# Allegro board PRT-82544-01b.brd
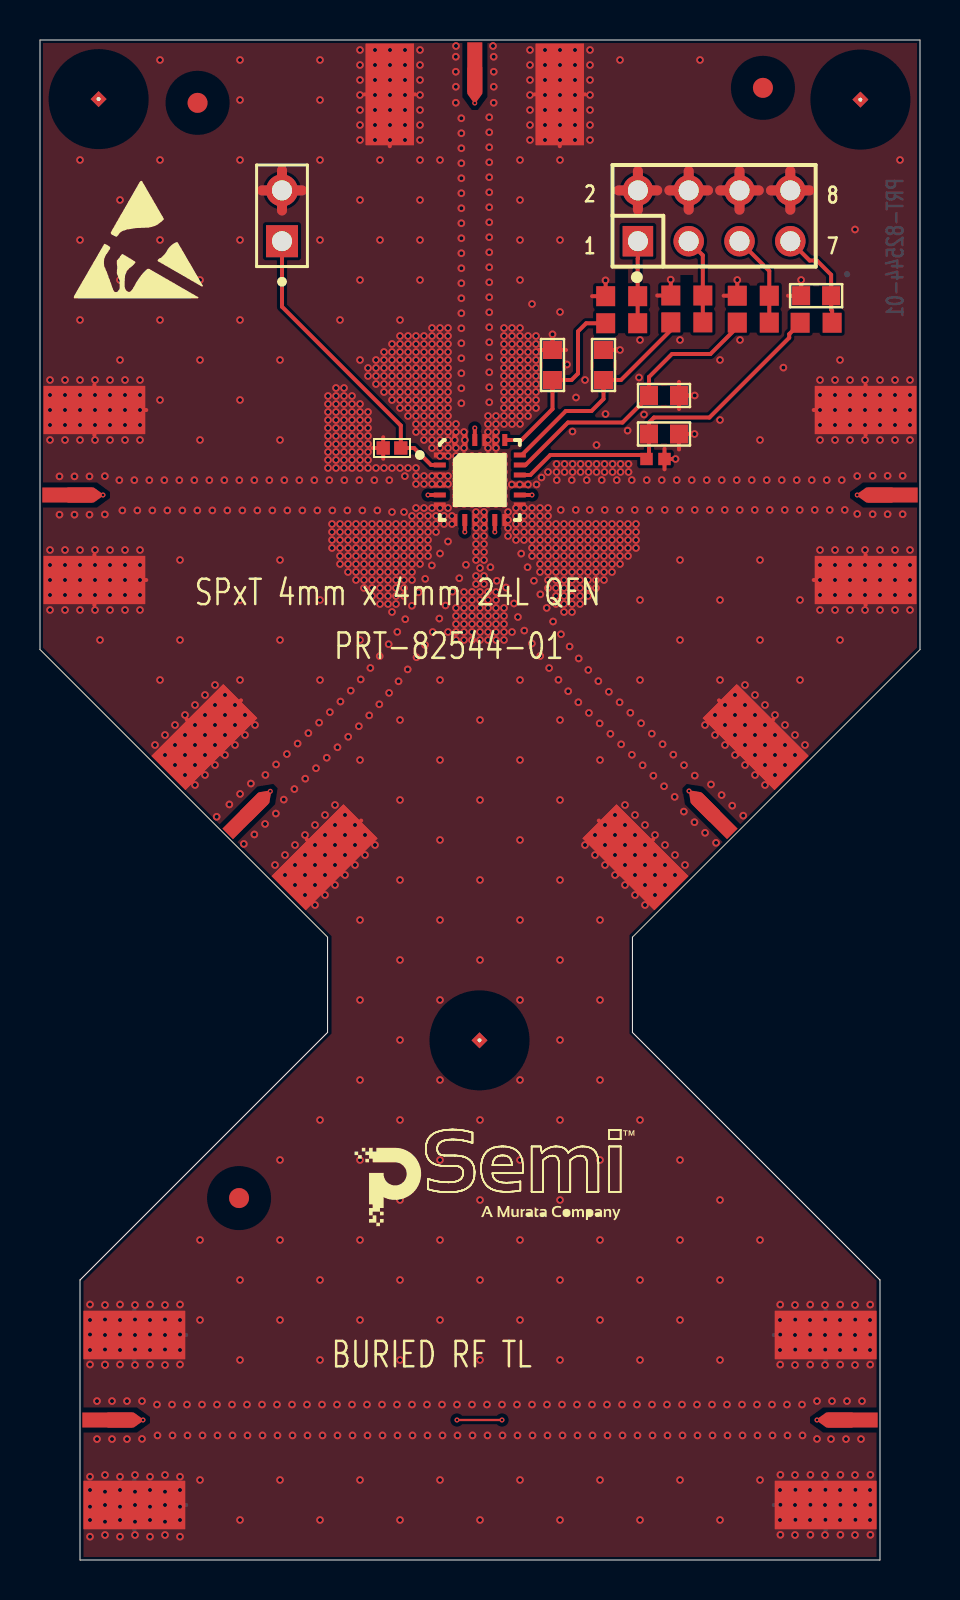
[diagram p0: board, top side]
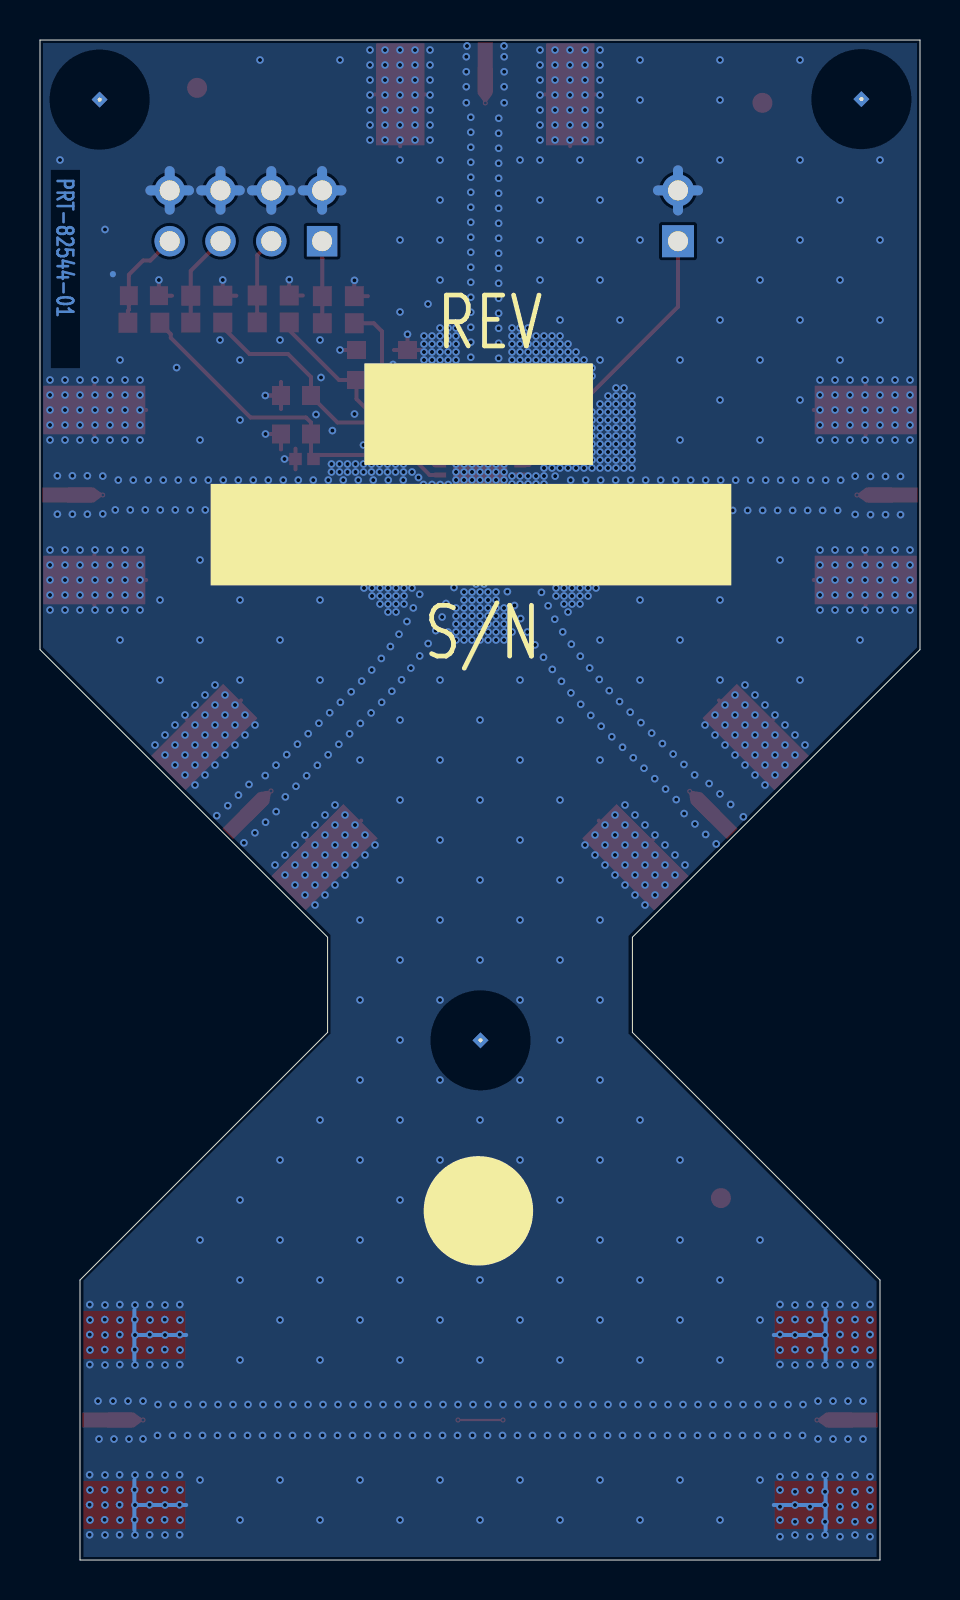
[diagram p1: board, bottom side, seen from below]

Outline 44 x 76 mm; copper layers: TOP, INNER LAYER 2, INNER LAYER 3, BOTTOM. Coordinates in mm from the lower left corner of the outline.
Outline path: 0,76 0,45.52 14.38,31.14 14.38,26.38 2,14 2,0 42,0 42,14 29.62,26.38 29.62,31.14 44,45.52 44,76 0,76

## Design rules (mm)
constraint set DEFAULT: 
nets with their own width: nets TE V1 V2 V3

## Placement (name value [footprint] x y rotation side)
C1  -  [CAPC1608X90N]  25.62 59.75 90 top
C2  -  [CAPC1608X90N]  28.18 59.75 90 top
C3  -  [CAPC1608X90N]  31.2 58.23 0 top
C4  -  [CAPC1608X90N]  31.2 56.3 0 top
C5  -  [CAPC1608X90N]  38.81 63.21 180 top
C7  -  [CAPC1005X55N]  30.77 55.05 0 top
J1  -  [SULLINS_PBC01DABN]  12.1 65.94 0 top
J2  -  [HDR2X4]  29.9 65.94 0 top
NOREF  -  []  0 76 0 top
NOREF#2  -  [unnamed#2]  21.98 25.98 0 top
NOREF#3  -  [unnamed#2]  2.93 73.05 0 top
NOREF#4  -  []  4.9 65.8 0 top
NOREF#5  -  [unnamed#2]  36.15 73.61 0 top
NOREF#6  -  []  -179.88 -98.6 0 top
NOREF#7  -  []  42 0 90 top
NOREF#8  -  []  57.15 54.8 0 top
NOREF#9  -  []  -191.92 -127.32 0 top
NOREF#10  -  [unnamed#2]  41.02 73.02 0 top
NOREF#11  -  [unnamed#2]  9.95 18.1 0 top
NOREF#12  -  []  -46.58 -55.22 0 top
NOREF#13  -  []  15.72 16.61 0 top
NOREF#14  -  [unnamed#2]  7.88 72.86 0 top
NOREF#15  -  []  22.12 17.4 180 bottom
NOREF#16  -  []  3.36 41.06 180 bottom
R1  -  [RESC1608X55N]  29.08 61.84 0 top
R2  -  [RESC1608X55N]  29.08 63.19 180 top
R3  -  [RESC1608X55N]  32.34 61.88 0 top
R4  -  [RESC1608X55N]  32.34 63.22 180 top
R5  -  [RESC1608X55N]  35.66 61.87 0 top
R6  -  [RESC1608X55N]  35.66 63.21 180 top
R7  -  [RESC1608X55N]  38.81 61.86 0 top
R8  -  [RESC1005X40N]  17.6 55.6 0 top
RF1  -  [JOHNSON_142-0701-851]  44 53.25 0 top
RF2  -  [JOHNSON_142-0701-851]  34.7 36.22 315 top
RF3  -  [JOHNSON_142-0701-851]  9.3 36.22 225 top
RF4  -  [JOHNSON_142-0701-851]  0 53.25 180 top
RFC  -  [JOHNSON_142-0701-851]  21.74 76 90 top
RFCAL1  -  [JOHNSON_142-0701-851]  2 7 180 top
RFCAL2  -  [JOHNSON_142-0701-851]  42 7 0 top
U1  -  [QFN50P400X400X75-25N]  21.99 54 0 top

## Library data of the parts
C1-C5 C7 = CAP_A
J1 = HDR_1X2_M
J2 = CN_PBC04DAAN
R1-R8 = RES
RF1-RF4 RFC RFCAL1 RFCAL2 = JOHNSON_2
U1 = IP_25L_0

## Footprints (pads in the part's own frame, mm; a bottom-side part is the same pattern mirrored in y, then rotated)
CAPC1005X55N
  rect 0.62x0.62 smd: 1(-0.45,0) 2(0.45,0)
CAPC1608X90N
  rect 0.9x0.95 smd: 1(-0.75,0) 2(0.75,0)
HDR2X4
  rect 1.524x1.524 hole 1: 1(0,0)
  round 1.524 hole 1: 2(0,2.54) 3(2.54,0) 4(2.54,2.54) 5(5.08,0) 6(5.08,2.54) 7(7.62,0) 8(7.62,2.54)
JOHNSON_142-0701-851
  rect 2.5x0.75 smd: 1(-1.369,0)
  rect 5.08x2.413 smd: 2(-2.719,4.25) 3(-2.719,-4.25) 4(-2.719,4.25) 5(-2.719,-4.25)
QFN50P400X400X75-25N
  rect 0.6x0.25 smd: 1(-2,1.25) 2(-2,0.75) 3(-2,0.25) 4(-2,-0.25) 5(-2,-0.75) 6(-2,-1.25) 13(2,-1.25) 14(2,-0.75) 15(2,-0.25) 16(2,0.25) 17(2,0.75) 18(2,1.25)
  rect 0.25x0.6 smd: 7(-1.25,-2) 8(-0.75,-2) 9(-0.25,-2) 10(0.25,-2) 11(0.75,-2) 12(1.25,-2) 19(1.25,2) 20(0.75,2) 21(0.25,2) 22(-0.25,2) 23(-0.75,2) 24(-1.25,2)
  rrect 2.7x2.7 smd: 25(0,0)
RESC1005X40N
  rect 0.67x0.67 smd: 1(-0.44,0) 2(0.44,0)
RESC1608X55N
  rect 0.95x1 smd: 1(-0.8,0) 2(0.8,0)
SULLINS_PBC01DABN
  rect 1.6x1.6 hole 1: 1(0,0)
  round 1.6 hole 1: 2(0,2.54)
unnamed#2
  custom 0.2x0.2 hole 3.8 unplated: (0,0)

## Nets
GND: C1.2 C2.2 C3.2 C4.2 C5.2 C7.2 J1.2 J2.2 J2.4 J2.6 J2.8 R2.2 R4.2 R6.2 R8.1 RF1.2 RF1.3 RF1.4 RF1.5(GND#5) RF2.2 RF2.3 RF2.4 RF2.5(GND#5) RF3.2 RF3.3 RF3.4 RF3.5(GND#5) RF4.2 RF4.3 RF4.4 RF4.5(GND#5) RFC.2 RFC.3 RFC.4 RFC.5(GND#5) RFCAL1.2 RFCAL1.3 RFCAL1.4 RFCAL1.5(GND#5) RFCAL2.2 RFCAL2.3 RFCAL2.4 RFCAL2.5(GND#5) U1.1 U1.3 U1.4 U1.6 U1.7 U1.9 U1.10 U1.12 U1.13 U1.15 U1.20 U1.21 U1.23 U1.24 U1.25
V1: C3.1 R5.1 U1.17
V2: C2.1 R3.1 U1.18
V3: C1.1 R1.1 U1.19
VDD: C4.1 C7.1 R7.1 U1.16(VDD)
RF1: RF1.1 U1.14
RF2: RF2.1 U1.11
RF3: RF3.1 U1.8
RF4: RF4.1 U1.5
RFC: RFC.1 U1.22
TE: J1.1 R8.2 U1.2
N6631865: RFCAL1.1 RFCAL2.1
N6649358: C5.1 J2.7 R7.2
N6649402: J2.1 R1.2 R2.1
N6649481: J2.5 R5.2 R6.1
N6649490: J2.3 R3.2 R4.1

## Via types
v1: diameter 0.381, hole 0.203, TOP to BOTTOM, 1700 vias
v2: diameter 0.254, hole 0.127, TOP to INNER LAYER 2, 14 vias

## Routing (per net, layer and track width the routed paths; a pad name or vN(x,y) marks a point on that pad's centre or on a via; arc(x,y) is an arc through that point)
GND: length 165.3
  TOP w0.2: 41.28,47.74 RF1.3 ; RF1.3 38.69,49 ; RF1.3 41.28,50.26 ; 27.6,63.19 R2.2 28.28,63.89 ; 2.72,47.74 RF4.2 ; RF4.2 2.72,50.26 ; RF4.2 5.31,49 ; RF4.3 5.31,57.5 ; RF4.3 2.72,56.24 ; RF4.3 2.72,58.76 ; C1.2 v1(25.62,61.29) ; C1.2 26.3,60.5 ; C1.2 24.95,60.5 ; 27.94,36.97 RF2.3 ; RF2.3 30.66,36.03 ; RF2.3 28.88,34.25 ; 13.34,36.03 RF3.2 ; RF3.2 16.06,36.97 ; RF3.2 15.12,34.25 ; 34.18,63.21 R6.2 34.86,63.92 ; 25.99,70.69 RFC.3 ; RFC.3 24.73,73.28 ; RFC.3 27.25,73.28 ; C3.2 v1(32.74,58.23) ; C3.2 31.95,58.9 ; C3.2 31.95,57.55 ; C3.2 32.6,58.23 ; 7.33,42.04 RF3.3 ; RF3.3 9.11,40.26 ; RF3.3 10.05,42.98 ; 38.69,57.5 RF1.2 ; RF1.2 41.28,56.24 ; RF1.2 41.28,58.76 ; 31.23,54.54 C7.2 ; C7.2 31.74,55.05 ; C7.2 31.23,55.56 ; R8.1 17.16,56.14 ; R8.1 17.16,55.06 ; R8.1 16.62,55.6 ; RF2.2 36.67,42.04 ; RF2.2 34.89,40.26 ; RF2.2 33.95,42.98 ; RFC.2 18.75,73.28 ; RFC.2 17.49,70.69 ; RFC.2 16.23,73.28 ; 37.4,63.21 C5.2 38.06,63.89 ; 30.86,63.22 R4.2 31.54,63.93 ; 31.95,55.53 C4.2 v1(32.73,56.3) ; C2.2 v1(29,60.5)
  TOP w0.5: 34.01,68.48 J2.6 ; J2.6 35.94,68.48 ; J2.6 34.98,67.51 ; J2.6 34.98,69.45 ; J2.2 29.9,69.45 ; J2.2 30.86,68.48 ; J2.2 28.93,68.48 ; J2.2 29.9,67.51 ; J2.4 32.44,69.45 ; J2.4 32.44,67.51 ; J2.4 33.4,68.48 ; J2.4 31.47,68.48 ; J1.2 12.1,69.48 ; J1.2 12.1,67.48 ; J1.2 13.1,68.48 ; J1.2 11.1,68.48 ; J2.8 37.52,69.45 ; J2.8 37.52,67.51 ; J2.8 38.48,68.48 ; J2.8 36.55,68.48
  INNER LAYER 2 w0.5: J2.2 29.9,69.45 ; J2.2 28.93,68.48 ; J2.2 30.86,68.48 ; J2.2 29.9,67.51 ; 34.98,67.51 J2.6 ; J2.6 34.98,69.45 ; J2.6 35.94,68.48 ; J2.6 34.01,68.48 ; J2.8 38.48,68.48 ; J2.8 37.52,69.45 ; J2.8 36.55,68.48 ; J2.8 37.52,67.51 ; J2.4 32.44,69.45 ; J2.4 31.47,68.48 ; J2.4 33.4,68.48 ; J2.4 32.44,67.51 ; 11.1,68.48 J1.2 ; J1.2 12.1,69.48 ; J1.2 13.1,68.48 ; J1.2 12.1,67.48
  INNER LAYER 3 w0.5: 36.55,68.48 J2.8 ; J2.8 38.48,68.48 ; J2.8 37.52,69.45 ; J2.8 37.52,67.51 ; J1.2 12.1,69.48 ; J1.2 12.1,67.48 ; J1.2 11.1,68.48 ; J1.2 13.1,68.48 ; 34.01,68.48 J2.6 ; J2.6 34.98,67.51 ; J2.6 35.94,68.48 ; J2.6 34.98,69.45 ; 32.44,67.51 J2.4 ; J2.4 32.44,69.45 ; J2.4 31.47,68.48 ; J2.4 33.4,68.48 ; 28.93,68.48 J2.2 ; J2.2 29.9,69.45 ; J2.2 29.9,67.51 ; J2.2 30.86,68.48
  BOTTOM w0.2: 39.28,9.99 RFCAL2.2 ; RFCAL2.2 39.28,12.51 ; RFCAL2.2 36.69,11.25 ; 36.69,2.75 RFCAL2.3 ; RFCAL2.3 39.28,4.01 ; RFCAL2.3 39.28,1.49 ; RFCAL1.2 4.72,4.01 ; RFCAL1.2 7.31,2.75 ; RFCAL1.2 4.72,1.49 ; 4.72,9.99 RFCAL1.3 ; RFCAL1.3 7.31,11.25 ; RFCAL1.3 4.72,12.51
  BOTTOM w0.305: 40.36,64.29 40.36,64.29
  BOTTOM w0.5: 34.98,67.51 J2.6 ; J2.6 34.01,68.48 ; J2.6 35.94,68.48 ; J2.6 34.98,69.45 ; 28.93,68.48 J2.2 ; J2.2 30.86,68.48 ; J2.2 29.9,69.45 ; J2.2 29.9,67.51 ; J2.8 37.52,69.45 ; J2.8 37.52,67.51 ; J2.8 38.48,68.48 ; J2.8 36.55,68.48 ; J2.4 32.44,69.45 ; J2.4 31.47,68.48 ; J2.4 33.4,68.48 ; J2.4 32.44,67.51 ; J1.2 13.1,68.48 ; J1.2 12.1,69.48 ; J1.2 12.1,67.48 ; J1.2 11.1,68.48
  vias: v1(0.5,59) v1(0.5,58.25) v1(0.5,57.5) v1(0.5,56.75) v1(0.5,56) v1(0.5,50.5) v1(0.5,49.75) v1(0.5,49) v1(0.5,48.25) v1(0.5,47.5) v1(0.97,54.18) v1(0.97,52.27) v1(1.25,59) v1(1.25,58.25) v1(1.25,57.5) v1(1.25,56.75) v1(1.25,56) v1(1.25,50.5) v1(1.25,49.75) v1(1.25,49) v1(1.25,48.25) v1(1.25,47.5) v1(1.72,54.18) v1(1.72,52.27) v1(2,70) v1(2,66) v1(2,62) v1(2,59) v1(2,58.25) v1(2,57.5) v1(2,56.75) v1(2,56) v1(2,50.5) v1(2,49.75) v1(2,49) v1(2,48.25) v1(2,47.5) v1(2.47,54.18) v1(2.47,52.27) v1(2.5,12.77) v1(2.5,12) v1(2.5,11.27) v1(2.5,10.5) v1(2.5,9.77) v1(2.5,4.16) v1(2.5,3.5) v1(2.5,2.66) v1(2.5,2) v1(2.5,1.16) v1(2.75,59) v1(2.75,58.25) v1(2.75,57.5) v1(2.75,56.75) v1(2.75,56) v1(2.75,50.5) v1(2.75,49.75) v1(2.75,49) v1(2.75,48.25) v1(2.75,47.5) v1(2.85,7.95) v1(2.85,6.05) v1(3,46) v1(3.24,54.19) v1(3.24,52.28) v1(3.25,12.75) v1(3.25,12.02) v1(3.25,11.25) v1(3.25,10.52) v1(3.25,9.77) v1(3.25,9.75) v1(3.25,4.25) v1(3.25,3.41) v1(3.25,2.75) v1(3.25,1.91) v1(3.25,1.25) v1(3.5,59) v1(3.5,58.25) v1(3.5,57.5) v1(3.5,56.75) v1(3.5,56) v1(3.5,50.5) v1(3.5,49.75) v1(3.5,49) v1(3.5,48.25) v1(3.5,47.5) v1(3.6,7.95) v1(3.6,6.05) v1(4,68) v1(4,64) v1(4,60) v1(3.97,53.99) v1(4,12.77) v1(4,12) v1(4,11.27) v1(4,10.5) v1(4,9.77) v1(4,4.16) v1(4,3.5) v1(4,2.66) v1(4,2) v1(4,1.16) v1(4.12,52.48) v1(4.25,59) v1(4.25,58.25) v1(4.25,57.5) v1(4.25,56.75) v1(4.25,56) v1(4.25,50.5) v1(4.25,49.75) v1(4.25,49) v1(4.25,48.25) v1(4.25,47.5) v1(4.35,7.95) v1(4.35,6.05) v1(4.72,53.99) v1(4.75,12.75) v1(4.75,12.02) v1(4.75,11.25) v1(4.75,10.52) v1(4.75,9.75) v1(4.75,4.25) v1(4.75,3.41) v1(4.75,2.75) v1(4.75,1.91) v1(4.75,1.25) v1(4.87,52.48) v1(5,59) v1(5,58.25) v1(5,57.5) v1(5,56.75) v1(5,56) v1(5,50.5) v1(5,49.75) v1(5,49) v1(5,48.25) v1(5,47.5) v1(5.1,7.95) v1(5.1,6.05) v1(5.47,53.99) v1(5.5,12.77) v1(5.5,12) v1(5.5,11.27) v1(5.5,10.5) v1(5.5,9.77) v1(5.5,4.16) v1(5.5,3.5) v1(5.5,2.66) v1(5.5,2) v1(5.5,1.16) v1(5.62,52.48) v1(5.75,40.75) v1(5.85,7.77) v1(5.88,6.23) v1(6,75) v1(6,70) v1(6,66) v1(6,62) v1(6,58) v1(6,44) v1(6.22,53.99) v1(6.25,41.25) v1(6.25,40.25) v1(6.25,12.75) v1(6.25,12.02) v1(6.25,11.25) v1(6.25,10.52) v1(6.25,9.75) v1(6.25,4.25) v1(6.25,3.41) v1(6.25,2.75) v1(6.25,1.91) v1(6.25,1.25) v1(6.37,52.48) v1(6.6,7.77) v1(6.62,6.23) v1(6.75,41.75) v1(6.75,40.75) v1(6.75,39.75) v1(6.97,53.99) v1(7,50) v1(7,46) v1(7,12.77) v1(7,12) v1(7,11.27) v1(7,10.5) v1(7,9.77) v1(7,4.16) v1(7,3.5) v1(7,2.66) v1(7,2) v1(7,1.16) v1(7.12,52.48) v1(7.25,42.25) v1(7.25,41.25) v1(7.25,40.25) v1(7.25,39.25) v1(7.35,7.77) v1(7.38,6.23) v1(7.72,53.99) v1(7.75,42.75) v1(7.75,41.75) v1(7.75,40.75) v1(7.75,39.75) v1(7.75,38.75) v1(7.87,52.48) v1(8,64) v1(8,60) v1(8,56) v1(8,16) v1(8,12) v1(8,4) v1(8.1,7.77) v1(8.12,6.23) v1(8.25,43.25) v1(8.25,42.25) v1(8.25,41.25) v1(8.25,40.25) v1(8.25,39.25) v1(8.47,53.99) v1(8.62,52.48) v1(8.75,43.75) v1(8.75,42.75) v1(8.75,41.75) v1(8.75,40.75) v1(8.75,39.75) v1(8.83,37.16) v1(8.85,7.77) v1(8.88,6.23) v1(9.22,53.99) v1(9.25,43.25) v1(9.25,42.25) v1(9.25,41.25) v1(9.25,40.25) v1(9.37,52.48) v1(9.47,37.78) v1(9.6,7.77) v1(9.62,6.23) v1(9.75,42.75) v1(9.75,41.75) v1(9.75,40.75) v1(10,75) v1(10,73) v1(10,70) v1(10,66) v1(10,62) v1(10,58) v1(9.97,53.99) v1(10,48) v1(10,44) v1(10,38.3) v1(10,14) v1(10,10) v1(10,2) v1(10.12,52.48) v1(10.25,42.25) v1(10.25,41.25) v1(10.19,35.8) v1(10.35,7.77) v1(10.38,6.23) v1(10.54,38.82) v1(10.72,53.99) v1(10.72,36.28) v1(10.75,41.75) v1(10.87,52.48) v1(11.1,7.77) v1(11.12,6.23) v1(11.27,39.25) v1(11.25,36.8) v1(11.47,53.99) v1(11.62,52.48) v1(11.8,39.78) v1(11.79,37.32) v1(11.75,34.75) v1(11.85,7.77) v1(11.88,6.23) v1(12,60) v1(12,56) v1(12,50) v1(12,46) v1(12,20) v1(12,16) v1(12,12) v1(12,4) v1(12.22,53.99) v1(12.19,38.02) v1(12.25,35.25) v1(12.25,34.25) v1(12.34,40.3) v1(12.37,52.48) v1(12.6,7.77) v1(12.62,6.23) v1(12.72,38.55) v1(12.75,35.75) v1(12.75,34.75) v1(12.75,33.75) v1(12.88,40.82) v1(12.97,53.99) v1(13.12,52.48) v1(13.25,36.25) v1(13.25,35.25) v1(13.25,34.25) v1(13.25,33.25) v1(13.26,39.07) v1(13.35,7.77) v1(13.42,41.34) v1(13.38,6.23) v1(13.72,53.99) v1(13.8,39.59) v1(13.75,36.75) v1(13.75,35.75) v1(13.75,34.75) v1(13.75,33.75) v1(13.75,32.75) v1(13.87,52.48) v1(14,75) v1(14,73) v1(14,70) v1(14,66) v1(14,48) v1(14,44) v1(13.96,41.87) v1(14,22) v1(14,14) v1(14,10) v1(14,2) v1(14.1,7.77) v1(14.12,6.23) v1(14.25,37.25) v1(14.25,36.25) v1(14.25,35.25) v1(14.25,34.25) v1(14.25,33.25) v1(14.34,40.11) v1(14.4,58.2) v1(14.4,57.8) v1(14.4,57.4) v1(14.4,57) v1(14.4,56.6) v1(14.4,56.2) v1(14.4,55.8) v1(14.4,55.4) v1(14.4,55) v1(14.4,54.6) v1(14.47,53.99) v1(14.49,42.39) v1(14.62,52.48) v1(14.6,51.8) v1(14.6,51.4) v1(14.6,51) v1(14.6,50.6) v1(14.8,58.6) v1(14.8,58.2) v1(14.8,57.8) v1(14.8,57.4) v1(14.8,57) v1(14.8,56.6) v1(14.8,56.2) v1(14.8,55.8) v1(14.8,55.4) v1(14.8,55) v1(14.8,54.6) v1(14.75,37.75) v1(14.75,36.75) v1(14.75,35.75) v1(14.75,34.75) v1(14.75,33.75) v1(14.85,7.77) v1(14.87,40.64) v1(14.88,6.23) v1(15,62) v1(15,51.8) v1(15,51.4) v1(15,51) v1(15,50.6) v1(15,50.2) v1(15,49.8) v1(15.02,42.92) v1(15.2,58.6) v1(15.2,58.2) v1(15.2,57.8) v1(15.2,57.4) v1(15.2,57) v1(15.2,56.6) v1(15.2,56.2) v1(15.2,55.8) v1(15.2,55.4) v1(15.2,55) v1(15.2,54.6) v1(15.22,53.99) v1(15.25,37.25) v1(15.25,36.25) v1(15.25,35.25) v1(15.25,34.25) v1(15.37,52.48) v1(15.4,51.8) v1(15.4,51.4) v1(15.4,51) v1(15.4,50.6) v1(15.4,50.2) v1(15.4,49.8) v1(15.4,49.4) v1(15.41,41.16) v1(15.54,43.47) v1(15.6,58.2) v1(15.6,57.8) v1(15.6,57.4) v1(15.6,57) v1(15.6,56.6) v1(15.6,56.2) v1(15.6,55.8) v1(15.6,55.4) v1(15.6,55) v1(15.6,54.6) v1(15.6,7.77) v1(15.62,6.23) v1(15.8,51.8) v1(15.8,51.4) v1(15.8,51) v1(15.8,50.6) v1(15.8,50.2) v1(15.8,49.8) v1(15.8,49.4) v1(15.8,49) v1(15.75,36.75) v1(15.75,35.75) v1(15.75,34.75) v1(15.94,41.69) v1(16,75.5) v1(16,74.75) v1(16,74) v1(16,73.25) v1(16,72.5) v1(16,71.75) v1(16,71) v1(16,68) v1(16,64) v1(16,60) v1(16,57.8) v1(16,57.4) v1(16,57) v1(16,56.6) v1(16,56.2) v1(16,55.8) v1(16,55.4) v1(16,55) v1(16,54.6) v1(15.97,53.99) v1(16,46) v1(16.04,44.03) v1(16,40) v1(16,32) v1(16,28) v1(16,24) v1(16,20) v1(16,16) v1(16,12) v1(16,4) v1(16.12,52.48) v1(16.2,51.8) v1(16.2,51.4) v1(16.2,51) v1(16.2,50.6) v1(16.2,50.2) v1(16.2,49.8) v1(16.2,49.4) v1(16.2,49) v1(16.2,48.6) v1(16.25,36.25) v1(16.25,35.25) v1(16.35,7.77) v1(16.4,59.6) v1(16.4,59.2) v1(16.4,57.4) v1(16.4,57) v1(16.4,56.6) v1(16.4,56.2) v1(16.4,55.8) v1(16.4,55.4) v1(16.4,55) v1(16.4,54.6) v1(16.38,6.23) v1(16.52,44.6) v1(16.46,42.23) v1(16.6,51.8) v1(16.6,51.4) v1(16.6,51) v1(16.6,50.6) v1(16.6,50.2) v1(16.6,49.8) v1(16.6,49.4) v1(16.6,49) v1(16.6,48.6) v1(16.6,48.2) v1(16.72,53.99) v1(16.75,75.5) v1(16.75,74.75) v1(16.75,74) v1(16.75,73.25) v1(16.75,72.5) v1(16.75,71.75) v1(16.75,71) v1(16.8,60) v1(16.8,59.6) v1(16.8,59.2) v1(16.8,58.8) v1(16.8,54.6) v1(16.75,35.75) v1(16.87,52.48) v1(17,70) v1(17,66) v1(17,51.8) v1(17,51.4) v1(17,51) v1(17,50.6) v1(17,50.2) v1(17,49.8) v1(17,49.4) v1(17,49) v1(17,48.6) v1(17,48.2) v1(17,47.8) v1(16.98,45.19) v1(16.97,42.79) v1(17.1,7.77) v1(17.12,6.23) v1(17.2,60.4) v1(17.2,60) v1(17.2,59.6) v1(17.2,59.2) v1(17.2,58.8) v1(17.2,58.4) v1(17.2,54.6) v1(17.4,51.8) v1(17.4,51.4) v1(17.4,51) v1(17.4,50.6) v1(17.4,50.2) v1(17.4,49.8) v1(17.4,49.4) v1(17.4,49) v1(17.4,48.6) v1(17.4,48.2) v1(17.4,47.8) v1(17.43,45.79) v1(17.5,75.5) v1(17.5,74.75) v1(17.5,74) v1(17.5,73.25) v1(17.5,72.5) v1(17.5,71.75) v1(17.5,71) v1(17.47,53.99) v1(17.45,43.35) v1(17.6,60.8) v1(17.6,60.4) v1(17.6,60) v1(17.6,59.6) v1(17.6,59.2) v1(17.6,58.8) v1(17.6,58.4) v1(17.6,58) v1(17.6,54.6) v1(17.6,52.4) v1(17.6,47.4) v1(17.8,51.8) v1(17.8,51.4) v1(17.8,51) v1(17.8,50.6) v1(17.8,50.2) v1(17.8,49.8) v1(17.8,49.4) v1(17.8,49) v1(17.8,48.6) v1(17.8,48.2) v1(17.8,47.8) v1(17.85,7.77) v1(17.86,46.4) v1(17.93,43.94) v1(17.88,6.23) v1(18,62) v1(18,61.2) v1(18,60.8) v1(18,60.4) v1(18,60) v1(18,59.6) v1(18,59.2) v1(18,58.8) v1(18,58.4) v1(18,58) v1(18,57.6) v1(18,54.6) v1(18,42) v1(18,38) v1(18,34) v1(18,30) v1(18,26) v1(18,22) v1(18,18) v1(18,14) v1(18,10) v1(18,2) v1(18.25,75.5) v1(18.25,74.75) v1(18.25,74) v1(18.25,73.25) v1(18.25,72.5) v1(18.25,71.75) v1(18.25,71) v1(18.24,54.19) v1(18.2,52.4) v1(18.2,51.8) v1(18.2,51.4) v1(18.2,51) v1(18.2,50.6) v1(18.2,50.2) v1(18.2,49.8) v1(18.2,49.4) v1(18.2,49) v1(18.2,48.6) v1(18.2,48.2) v1(18.26,47.04) v1(18.4,61.2) v1(18.4,60.8) v1(18.4,60.4) v1(18.4,60) v1(18.4,59.6) v1(18.4,59.2) v1(18.4,58.8) v1(18.4,58.4) v1(18.4,58) v1(18.4,57.6) v1(18.4,57.2) v1(18.4,54.6) v1(18.39,44.53) v1(18.6,52.2) v1(18.6,51.8) v1(18.6,51.4) v1(18.6,51) v1(18.6,50.6) v1(18.6,50.2) v1(18.6,49.8) v1(18.6,49.4) v1(18.6,49) v1(18.59,47.71) v1(18.6,7.77) v1(18.62,6.23) v1(18.8,61.2) v1(18.8,60.8) v1(18.8,60.4) v1(18.8,60) v1(18.8,59.6) v1(18.8,59.2) v1(18.8,58.8) v1(18.8,58.4) v1(18.8,58) v1(18.8,57.6) v1(18.8,57.2) v1(18.8,56.8) v1(18.8,56.4) v1(18.8,54.6) v1(18.8,54.2) v1(18.8,53.8) v1(18.8,52.6) v1(18.83,45.14) v1(18.93,48.38) v1(19,75.5) v1(19,74.75) v1(19,74) v1(19,73.25) v1(19,72.5) v1(19,71.75) v1(19,71) v1(19,70) v1(19,68) v1(19,66) v1(19,64) v1(19,52.2) v1(19,51.8) v1(19,51.4) v1(19,51) v1(19,50.6) v1(19,50.2) v1(19,49.8) v1(19.2,61.2) v1(19.2,60.8) v1(19.2,60.4) v1(19.2,60) v1(19.2,59.6) v1(19.2,59.2) v1(19.2,58.8) v1(19.2,58.4) v1(19.2,58) v1(19.2,57.6) v1(19.2,57.2) v1(19.2,56.8) v1(19.2,56.4) v1(19.2,56) v1(19.2,54.2) v1(19.2,53.8) v1(19.2,52.6) v1(19.26,49.06) v1(19.25,45.76) v1(19.4,52.2) v1(19.4,51.8) v1(19.4,51.4) v1(19.4,51) v1(19.4,50.6) v1(19.4,50.2) v1(19.35,7.77) v1(19.38,6.23) v1(19.6,61.6) v1(19.6,61.2) v1(19.6,60.8) v1(19.6,60.4) v1(19.6,60) v1(19.6,59.6) v1(19.6,59.2) v1(19.6,58.8) v1(19.6,58.4) v1(19.6,58) v1(19.6,57.6) v1(19.6,57.2) v1(19.6,56.8) v1(19.6,56.4) v1(19.6,56) v1(19.6,55.6) v1(19.6,54.2) v1(19.6,53.8) v1(19.6,52.6) v1(19.59,49.73) v1(19.63,46.4) v1(19.8,52.2) v1(19.8,51.8) v1(19.8,51.4) v1(20,70) v1(20,61.6) v1(20,61.2) v1(20,60.8) v1(20,60.4) v1(20,60) v1(20,59.6) v1(20,59.2) v1(20,58.8) v1(20,58.4) v1(20,58) v1(20,57.6) v1(20,57.2) v1(20,56.8) v1(20,56.4) v1(20,56) v1(20,55.6) v1(20,55.2) v1(20,54.2) v1(20,53.8) v1(20,52.6) v1(20,50.33) v1(19.97,47.07) v1(20,44) v1(20,40) v1(20,36) v1(20,32) v1(20,28) v1(20,24) v1(20,20) v1(20,16) v1(20,12) v1(20,4) v1(20.1,7.77) v1(20.12,6.23) v1(20.2,52.2) v1(20.2,51.8) v1(20.27,47.73) v1(20.4,61.6) v1(20.4,61.2) v1(20.4,60.8) v1(20.4,60.4) v1(20.4,60) v1(20.4,59.6) v1(20.4,59.2) v1(20.4,58.8) v1(20.4,58.4) v1(20.4,58) v1(20.4,57.6) v1(20.4,57.2) v1(20.4,56.8) v1(20.4,56.4) v1(20.4,56) v1(20.4,55.6) v1(20.4,55.2) v1(20.4,54.2) v1(20.4,53.8) v1(20.4,52.6) v1(20.4,50.92) v1(20.4,46.4) v1(20.6,52.2) v1(20.6,51.8) v1(20.63,48.42) v1(20.74,56) v1(20.8,75.7) v1(20.79,75.16) v1(20.79,74.41) v1(20.79,73.66) v1(20.79,72.86) v1(20.8,56.8) v1(20.8,56.4) v1(20.8,55.6) v1(20.8,55.2) v1(20.8,54.8) v1(20.8,54.4) v1(20.8,54) v1(20.8,53.6) v1(20.8,53.2) v1(20.8,52.8) v1(20.8,47.6) v1(20.8,47.2) v1(20.8,46.8) v1(20.8,46.4) v1(20.8,46) v1(20.85,7.77) v1(20.88,6.23) v1(20.97,49.09) v1(21.07,72.09) v1(21.07,71.34) v1(21.07,70.59) v1(21.07,69.84) v1(21.07,69.09) v1(21.07,68.34) v1(21.07,67.59) v1(21.07,66.84) v1(21.07,66.09) v1(21.07,65.34) v1(21.07,64.59) v1(21.07,63.84) v1(21.07,63.09) v1(21.07,62.34) v1(21.07,61.59) v1(21.07,60.84) v1(21.07,60.09) v1(21.07,59.34) v1(21.07,58.59) v1(21.07,57.84) v1(21.2,56.4) v1(21.24,56) v1(21.2,55.6) v1(21.2,55.2) v1(21.2,54.8) v1(21.2,54.4) v1(21.2,54) v1(21.2,53.6) v1(21.2,53.2) v1(21.2,52.8) v1(21.2,48.4) v1(21.2,48) v1(21.2,47.6) v1(21.2,47.2) v1(21.2,46.8) v1(21.2,46.4) v1(21.2,46) v1(21.3,49.76) v1(21.6,55.2) v1(21.6,54.8) v1(21.6,54.4) v1(21.6,54) v1(21.6,53.6) v1(21.6,53.2) v1(21.6,52.8) v1(21.6,48.4) v1(21.6,48) v1(21.6,47.6) v1(21.6,47.2) v1(21.6,46.8) v1(21.6,46.4) v1(21.6,46) v1(21.6,7.77) v1(21.62,6.23) v1(21.8,52.4) v1(21.8,52) v1(21.8,51.6) v1(21.8,51.2) v1(21.8,50.8) v1(21.8,50.4) v1(21.8,50) v1(21.8,49.2) v1(21.8,48.8) v1(22,55.2) v1(22,54.8) v1(22,54.4) v1(22,54) v1(22,53.6) v1(22,53.2) v1(22,52.8) v1(22,49.6) v1(22,48.4) v1(22,48) v1(22,47.6) v1(22,47.2) v1(22,46.8) v1(22,46.4) v1(22,46) v1(22,42) v1(22,38) v1(22,34) v1(22,30) v1(22,22) v1(22,18) v1(22,14) v1(22,10) v1(22,2) v1(22.2,52.4) v1(22.2,52) v1(22.2,51.6) v1(22.2,51.2) v1(22.2,50.8) v1(22.2,50.4) v1(22.2,50) v1(22.2,49.2) v1(22.2,48.8) v1(22.35,7.77) v1(22.4,57.2) v1(22.4,56.8) v1(22.4,56.4) v1(22.4,56) v1(22.4,55.6) v1(22.4,55.2) v1(22.4,54.8) v1(22.4,54.4) v1(22.4,54) v1(22.4,53.6) v1(22.4,53.2) v1(22.4,52.8) v1(22.4,48.4) v1(22.4,48) v1(22.4,47.6) v1(22.4,47.2) v1(22.4,46.8) v1(22.4,46.4) v1(22.4,46) v1(22.38,6.23) v1(22.46,72.14) v1(22.46,71.39) v1(22.46,70.64) v1(22.46,69.89) v1(22.46,69.14) v1(22.46,68.39) v1(22.46,67.64) v1(22.46,66.89) v1(22.46,66.14) v1(22.46,65.39) v1(22.46,64.64) v1(22.46,63.89) v1(22.46,63.14) v1(22.46,62.39) v1(22.46,61.64) v1(22.46,60.89) v1(22.46,60.14) v1(22.46,59.39) v1(22.46,58.64) v1(22.46,57.89) v1(22.52,49.64) v1(22.65,75.7) v1(22.68,75.16) v1(22.69,74.41) v1(22.69,73.66) v1(22.68,72.86) v1(22.8,57.2) v1(22.8,56.8) v1(22.8,56.4) v1(22.8,56) v1(22.8,55.6) v1(22.8,55.2) v1(22.8,54.8) v1(22.8,54.4) v1(22.8,54) v1(22.8,53.6) v1(22.8,53.2) v1(22.8,52.8) v1(22.84,48.96) v1(22.8,48.4) v1(22.8,48) v1(22.8,47.6) v1(22.8,47.2) v1(22.8,46.8) v1(22.8,46.4) v1(22.8,46) v1(23.1,7.77) v1(23.12,6.23) v1(23.2,61.6) v1(23.2,61.2) v1(23.2,60.8) v1(23.2,60.4) v1(23.2,60) v1(23.2,59.6) v1(23.2,59.2) v1(23.2,58.8) v1(23.2,58.4) v1(23.2,58) v1(23.2,57.6) v1(23.2,57.2) v1(23.2,56.8) v1(23.2,55.2) v1(23.2,54.8) v1(23.2,54.4) v1(23.2,54) v1(23.2,53.6) v1(23.2,53.2) v1(23.2,52.8) v1(23.2,47.6) v1(23.2,47.2) v1(23.2,46.8) v1(23.2,46.4) v1(23.2,46) v1(23.3,48.62) v1(23.4,52.4) v1(23.4,52) v1(23.4,51.6) v1(23.4,51.2) v1(23.6,61.6) v1(23.6,61.2) v1(23.6,60.8) v1(23.6,60.4) v1(23.6,60) v1(23.6,59.6) v1(23.6,59.2) v1(23.6,58.8) v1(23.6,58.4) v1(23.6,58) v1(23.6,57.6) v1(23.6,57.2) v1(23.6,56.8) v1(23.59,53.78) v1(23.6,46.4) v1(23.7,47.83) v1(23.8,52.6) v1(23.8,52.2) v1(23.8,51.8) v1(23.8,51.4) v1(23.8,51) v1(23.89,47.15) v1(23.85,7.77) v1(23.88,6.23) v1(24,70) v1(24,68) v1(24,66) v1(24,64) v1(24,61.6) v1(24,61.2) v1(24,60.8) v1(24,60.4) v1(24,60) v1(24,59.6) v1(24,59.2) v1(24,58.8) v1(24,58.4) v1(24,58) v1(24,57.6) v1(24,57.2) v1(24,56.8) v1(23.99,53.78) v1(24,44) v1(24,40) v1(24,36) v1(24,32) v1(24,28) v1(24,24) v1(24,20) v1(24,16) v1(24,12) v1(24,4) v1(24.06,50.32) v1(24.2,52.6) v1(24.2,52.2) v1(24.2,51.8) v1(24.2,51.4) v1(24.2,51) v1(24.21,46.47) v1(24.4,61.2) v1(24.4,60.8) v1(24.4,60.4) v1(24.4,60) v1(24.4,59.6) v1(24.4,59.2) v1(24.4,58.8) v1(24.4,58.4) v1(24.4,58) v1(24.4,57.6) v1(24.4,57.2) v1(24.4,53.77) v1(24.38,49.64) v1(24.5,75.5) v1(24.5,74.75) v1(24.5,74) v1(24.5,73.25) v1(24.5,72.5) v1(24.5,71.75) v1(24.5,71) v1(24.6,62.8) v1(24.6,52.6) v1(24.6,52.2) v1(24.6,51.8) v1(24.6,51.4) v1(24.6,51) v1(24.6,50.6) v1(24.6,50.2) v1(24.59,45.82) v1(24.6,7.77) v1(24.62,6.23) v1(24.7,48.96) v1(24.8,61.2) v1(24.8,60.8) v1(24.8,60.4) v1(24.8,60) v1(24.8,59.6) v1(24.8,59.2) v1(24.8,58.8) v1(24.8,58.4) v1(24.8,58) v1(24.8,57.6) v1(24.82,53.77) v1(25,52.6) v1(25,52.2) v1(25,51.8) v1(25,51.4) v1(25,51) v1(25,50.6) v1(25,50.2) v1(25,49.8) v1(25,49.4) v1(25.02,48.28) v1(25.01,45.2) v1(25.07,54.12) v1(25.25,75.5) v1(25.25,74.75) v1(25.25,74) v1(25.25,73.25) v1(25.25,72.5) v1(25.25,71.75) v1(25.25,71) v1(25.33,47.6) v1(25.4,54.4) v1(25.4,52.6) v1(25.4,52.2) v1(25.4,51.8) v1(25.4,51.4) v1(25.4,51) v1(25.4,50.6) v1(25.4,50.2) v1(25.4,49.8) v1(25.4,49.4) v1(25.4,49) v1(25.4,48.6) v1(25.35,7.77) v1(25.38,6.23) v1(25.46,44.6) v1(25.65,46.92) v1(25.82,54.8) v1(25.82,54.4) v1(25.84,54) v1(25.8,51.8) v1(25.8,51.4) v1(25.8,51) v1(25.8,50.6) v1(25.8,50.2) v1(25.8,49.8) v1(25.8,49.4) v1(25.8,49) v1(25.8,48.6) v1(25.8,48.2) v1(25.8,47.8) v1(25.92,44.01) v1(26,75.5) v1(26,74.75) v1(26,74) v1(26,73.25) v1(26,72.5) v1(26,71.75) v1(26,71) v1(26,70) v1(26,66) v1(26,62.4) v1(26.04,52.5) v1(26.05,46.29) v1(26,42) v1(26,38) v1(26,34) v1(26,30) v1(26,26) v1(26,22) v1(26,18) v1(26,14) v1(26,10) v1(26,2) v1(26.1,7.77) v1(26.12,6.23) v1(26.23,54.8) v1(26.23,54.4) v1(26.2,51.8) v1(26.2,51.4) v1(26.2,51) v1(26.2,50.6) v1(26.2,50.2) v1(26.2,49.8) v1(26.2,49.4) v1(26.2,49) v1(26.2,48.6) v1(26.2,48.2) v1(26.2,47.8) v1(26.2,47.4) v1(26.35,59.77) v1(26.41,43.44) v1(26.48,45.67) v1(26.62,56.42) v1(26.62,54.8) v1(26.62,54.4) v1(26.59,54) v1(26.6,51.8) v1(26.6,51.4) v1(26.6,51) v1(26.6,50.6) v1(26.6,50.2) v1(26.6,49.8) v1(26.6,49.4) v1(26.6,49) v1(26.6,48.6) v1(26.6,48.2) v1(26.6,47.8) v1(26.6,47.4) v1(26.75,75.5) v1(26.75,74.75) v1(26.75,74) v1(26.75,73.25) v1(26.75,72.5) v1(26.75,71.75) v1(26.75,71) v1(26.8,58.12) v1(26.79,52.5) v1(26.85,7.77) v1(26.93,45.08) v1(26.92,42.89) v1(26.88,6.23) v1(27.02,54.8) v1(27.02,54.4) v1(27,51.8) v1(27,51.4) v1(27,51) v1(27,50.6) v1(27,50.2) v1(27,49.8) v1(27,49.4) v1(27,49) v1(27,48.6) v1(27,48.2) v1(27,47.8) v1(27.25,59) v1(27.25,35.75) v1(27.34,54) v1(27.43,54.8) v1(27.43,54.4) v1(27.4,51.8) v1(27.4,51.4) v1(27.4,51) v1(27.4,50.6) v1(27.4,50.2) v1(27.4,49.8) v1(27.4,49.4) v1(27.4,49) v1(27.4,48.6) v1(27.4,48.2) v1(27.41,44.5) v1(27.45,42.36) v1(27.5,75.5) v1(27.5,74.75) v1(27.5,74) v1(27.5,73.25) v1(27.5,72.5) v1(27.5,71.75) v1(27.5,71) v1(27.49,52.5) v1(27.6,7.77) v1(27.62,6.23) v1(27.82,55.75) v1(27.82,54.8) v1(27.82,54.4) v1(27.8,51.8) v1(27.8,51.4) v1(27.8,51) v1(27.8,50.6) v1(27.8,50.2) v1(27.8,49.8) v1(27.8,49.4) v1(27.8,49) v1(27.8,48.6) v1(27.75,36.25) v1(27.75,35.25) v1(27.92,43.94) v1(27.98,41.83) v1(28,40) v1(28,32) v1(28,28) v1(28,24) v1(28,20) v1(28,16) v1(28,12) v1(28,4) v1(28.09,54) v1(28.23,54.8) v1(28.23,54.4) v1(28.24,52.5) v1(28.2,51.8) v1(28.2,51.4) v1(28.2,51) v1(28.2,50.6) v1(28.2,50.2) v1(28.2,49.8) v1(28.2,49.4) v1(28.2,49) v1(28.25,36.75) v1(28.25,35.75) v1(28.25,34.75) v1(28.28,63.98) v1(28.27,57.3) v1(28.35,7.77) v1(28.44,43.41) v1(28.38,6.23) v1(28.52,41.31) v1(28.62,54.8) v1(28.62,54.4) v1(28.6,51.8) v1(28.6,51.4) v1(28.6,51) v1(28.6,50.6) v1(28.6,50.2) v1(28.6,49.8) v1(28.6,49.4) v1(28.84,54) v1(28.75,37.25) v1(28.75,36.25) v1(28.75,35.25) v1(28.75,34.25) v1(29,75) v1(29.02,54.8) v1(29.02,54.4) v1(28.99,52.5) v1(29,51.8) v1(29,51.4) v1(29,51) v1(29,50.6) v1(29,50.2) v1(29,49.8) v1(28.98,42.89) v1(29.06,40.78) v1(29.1,7.77) v1(29.12,6.23) v1(29.25,37.75) v1(29.25,36.75) v1(29.25,35.75) v1(29.25,34.75) v1(29.25,33.75) v1(29.38,56.47) v1(29.43,54.8) v1(29.43,54.4) v1(29.4,51.8) v1(29.4,51.4) v1(29.4,51) v1(29.4,50.6) v1(29.4,50.2) v1(29.52,42.36) v1(29.59,54) v1(29.59,40.26) v1(29.74,52.5) v1(29.8,51.8) v1(29.8,51.4) v1(29.8,51) v1(29.8,50.6) v1(29.75,37.25) v1(29.75,36.25) v1(29.75,35.25) v1(29.75,34.25) v1(29.75,33.25) v1(29.85,7.77) v1(29.88,6.23) v1(30,61) v1(29.95,59.12) v1(30,48) v1(30,44) v1(30,22) v1(30,14) v1(30,10) v1(30,2) v1(30.05,41.84) v1(30.13,39.74) v1(30.2,57.27) v1(30.25,36.75) v1(30.25,35.75) v1(30.25,34.75) v1(30.25,33.75) v1(30.25,32.75) v1(30.34,54) v1(30.49,52.5) v1(30.59,41.32) v1(30.6,7.77) v1(30.62,6.23) v1(30.67,39.21) v1(30.75,36.25) v1(30.75,35.25) v1(30.75,34.25) v1(30.75,33.25) v1(31.09,54) v1(31.13,40.79) v1(31.24,52.5) v1(31.2,38.69) v1(31.25,35.75) v1(31.25,34.75) v1(31.25,33.75) v1(31.35,7.77) v1(31.38,6.23) v1(31.53,64.02) v1(31.66,40.27) v1(31.73,38.16) v1(31.77,55.05) v1(31.84,54) v1(31.75,35.25) v1(31.75,34.25) v1(32,61) v1(31.99,52.5) v1(32,50) v1(32,46) v1(32,20) v1(32,16) v1(32,12) v1(32,4) v1(32.1,7.77) v1(32.12,6.23) v1(32.2,39.74) v1(32.19,37.42) v1(32.25,34.75) v1(32.59,54) v1(32.74,52.5) v1(32.74,39.22) v1(32.72,36.89) v1(32.85,7.77) v1(32.88,6.23) v1(33,75) v1(33.25,41.75) v1(33.34,54) v1(33.25,36.36) v1(33.49,52.5) v1(33.55,38.78) v1(33.6,7.77) v1(33.62,6.23) v1(33.75,42.25) v1(33.75,41.25) v1(33.8,35.86) v1(34,60) v1(34,57) v1(34,48) v1(34,44) v1(34,18) v1(34,14) v1(34,10) v1(34,2) v1(34.09,54) v1(34.08,38.25) v1(34.24,52.5) v1(34.25,42.75) v1(34.25,41.75) v1(34.25,40.75) v1(34.35,7.77) v1(34.38,6.23) v1(34.61,37.72) v1(34.84,54) v1(34.75,43.25) v1(34.75,42.25) v1(34.75,41.25) v1(34.75,40.25) v1(34.86,64) v1(35,61) v1(34.99,52.5) v1(35.1,7.77) v1(35.12,6.23) v1(35.25,43.75) v1(35.25,42.75) v1(35.25,41.75) v1(35.25,40.75) v1(35.25,39.75) v1(35.16,37.22) v1(35.59,54) v1(35.74,52.5) v1(35.75,43.25) v1(35.75,42.25) v1(35.75,41.25) v1(35.75,40.25) v1(35.75,39.25) v1(35.85,7.77) v1(35.88,6.23) v1(36,56) v1(36,50) v1(36,46) v1(36,16) v1(36,4) v1(36.25,42.75) v1(36.25,41.75) v1(36.25,40.75) v1(36.25,39.75) v1(36.25,38.75) v1(36.34,54) v1(36.49,52.5) v1(36.6,7.77) v1(36.62,6.23) v1(36.75,42.25) v1(36.75,41.25) v1(36.75,40.25) v1(36.75,39.25) v1(37.01,12.77) v1(37,12) v1(37.01,11.27) v1(37,10.5) v1(37.01,9.77) v1(37.02,4.26) v1(37,3.5) v1(37.02,2.76) v1(37,2) v1(37.02,1.26) v1(37.09,54) v1(37.17,59.62) v1(37.24,52.5) v1(37.25,41.75) v1(37.25,40.75) v1(37.25,39.75) v1(37.35,7.77) v1(37.38,6.23) v1(37.84,54) v1(37.75,41.25) v1(37.75,40.25) v1(37.75,12.75) v1(37.76,12.02) v1(37.75,11.25) v1(37.76,10.52) v1(37.75,9.75) v1(37.75,4.25) v1(37.77,3.51) v1(37.75,2.75) v1(37.77,2.01) v1(37.75,1.25) v1(37.99,52.5) v1(38,48) v1(38,44) v1(38.06,64) v1(38.1,7.77) v1(38.12,6.23) v1(38.25,40.75) v1(38.51,12.77) v1(38.5,12) v1(38.51,11.27) v1(38.5,10.5) v1(38.51,9.77) v1(38.52,4.26) v1(38.5,3.5) v1(38.52,2.76) v1(38.5,2) v1(38.52,1.26) v1(38.59,54) v1(38.74,52.5) v1(38.85,7.95) v1(38.85,6.05) v1(39,59) v1(39,58.25) v1(39,57.5) v1(39,56.75) v1(39,56) v1(39,50.5) v1(39,49.75) v1(39,49) v1(39,48.25) v1(39,47.5) v1(39.25,12.75) v1(39.25,11.25) v1(39.25,9.75) v1(39.25,4.25) v1(39.25,2.75) v1(39.25,1.25) v1(39.34,54) v1(39.26,12.02) v1(39.26,10.52) v1(39.27,3.51) v1(39.27,2.01) v1(39.49,52.5) v1(39.6,7.95) v1(39.55,6.05) v1(39.75,59) v1(39.75,58.25) v1(39.75,57.5) v1(39.75,56.75) v1(39.75,56) v1(39.75,50.5) v1(39.75,49.75) v1(39.75,49) v1(39.75,48.25) v1(39.75,47.5) v1(40,60) v1(40,46) v1(40.01,12.77) v1(40,12) v1(40.01,11.27) v1(40,10.5) v1(40.01,9.77) v1(40.02,4.26) v1(40,3.5) v1(40.02,2.76) v1(40,2) v1(40.02,1.26) v1(40.09,54) v1(40.24,52.5) v1(40.3,6.05) v1(40.35,7.95) v1(40.5,59) v1(40.5,58.25) v1(40.5,57.5) v1(40.5,56.75) v1(40.5,56) v1(40.5,50.5) v1(40.5,49.75) v1(40.5,49) v1(40.5,48.25) v1(40.5,47.5) v1(40.75,66.53) v1(40.75,12.75) v1(40.76,12.02) v1(40.75,11.25) v1(40.76,10.52) v1(40.75,9.75) v1(40.75,4.25) v1(40.77,3.51) v1(40.75,2.75) v1(40.77,2.01) v1(40.75,1.25) v1(40.86,54.2) v1(40.86,52.3) v1(41.1,7.95) v1(41.05,6.05) v1(41.25,59) v1(41.25,58.25) v1(41.25,57.5) v1(41.25,56.75) v1(41.25,56) v1(41.25,50.5) v1(41.25,49.75) v1(41.25,49) v1(41.25,48.25) v1(41.25,47.5) v1(41.51,12.77) v1(41.5,12) v1(41.51,11.27) v1(41.5,10.5) v1(41.51,9.77) v1(41.52,4.26) v1(41.5,3.5) v1(41.52,2.76) v1(41.5,2) v1(41.52,1.26) v1(41.63,54.21) v1(41.63,52.29) v1(42,59) v1(42,58.25) v1(42,57.5) v1(42,56.75) v1(42,56) v1(42,50.5) v1(42,49.75) v1(42,49) v1(42,48.25) v1(42,47.5) v1(42.38,54.21) v1(42.38,52.29) v1(42.75,59) v1(42.75,58.25) v1(42.75,57.5) v1(42.75,56.75) v1(42.75,56) v1(42.75,50.5) v1(42.75,49.75) v1(42.75,49) v1(42.75,48.25) v1(42.75,47.5) v1(43,70) v1(43.13,54.21) v1(43.13,52.29) v1(43.5,59) v1(43.5,58.25) v1(43.5,57.5) v1(43.5,56.75) v1(43.5,56) v1(43.5,50.5) v1(43.5,49.75) v1(43.5,49) v1(43.5,48.25) v1(43.5,47.5)
V1: length 14.5
  TOP w0.2: R5.1 34.86,61.64 33.52,60.3 31.6,60.3 30.45,59.15 C3.1 30.45,58.2 29.13,56.88 26.4,56.88 24.28,54.75 U1.17
V2: length 11.1
  TOP w0.2: R3.1 31.54,61.49 29.05,59 C2.1 28.18,58.05 27.58,57.45 26.29,57.45 24.09,55.25 U1.18
V3: length 9.5
  TOP w0.2: U1.19 24.08,56 25.62,57.55 C1.1 26.57,59 26.9,59.33 26.9,61.43 27.31,61.84 R1.1
VDD: length 18.5
  TOP w0.2: R7.1 38.01,61.84 37.46,61.29 37.46,61.11 33.47,57.12 30.7,57.12 30.45,56.88 C4.1 30.45,55.17 30.32,55.05 30.12,55.25 25.51,55.25 24.51,54.25 U1.16
RF1: length 18.6
  TOP w0.114: RF1.1 v2(40.86,53.25)
  TOP w0.2: U1.14 v2(24.6,53.25)
  INNER LAYER 2 w0.089: v2(40.86,53.25) v2(24.6,53.25)
RF2: length 18.8
  TOP w0.114: v2(32.45,38.45) 32.81,38.11 RF2.1
  TOP w0.2: U1.11 v2(22.74,51.4)
  INNER LAYER 2 w0.089: v2(22.74,51.4) 25.03,46.52 25.03,46.52 arc(26.39,44.59) 27.97,42.84 31.55,39.35 32.29,38.62 32.29,38.61 v2(32.45,38.45)
RF3: length 18.7
  TOP w0.114: RF3.1 v2(11.52,38.44)
  TOP w0.2: U1.8 v2(21.24,51.4)
  INNER LAYER 2 w0.089: v2(21.24,51.4) 18.81,46.49 18.81,46.49 arc(17.03,44.05) 14.99,41.82 12.45,39.34 12.13,39.05 v2(11.52,38.44)
RF4: length 18.6
  TOP w0.114: RF4.1 2.89,53.25 v2(3.15,53.25)
  TOP w0.2: v2(19.4,53.25) 19.86,53.25 U1.5
  INNER LAYER 2 w0.089: v2(3.15,53.25) 3.3,53.25 3.3,53.25 19.2,53.25 19.2,53.25 v2(19.4,53.25)
RFC: length 18.6
  TOP w0.114: RFC.1 21.74,73.32 21.74,73.32 v2(21.74,72.85)
  TOP w0.2: U1.22 21.74,56.09 v2(21.74,56.6)
  INNER LAYER 2 w0.089: v2(21.74,72.85) 21.74,72.13 21.74,72.13 v2(21.74,56.6)
TE: length 15.1
  TOP w0.2: J1.1 12.1,62.66 18.04,56.72 R8.2 18.7,55.6 19.55,54.75 U1.2
N6631865: length 37.3
  TOP w0.114: RFCAL2.1 v2(38.85,7) ; RFCAL1.1 v2(5.15,7) ; v2(20.85,7) v2(23.1,7)
  INNER LAYER 2 w0.089: v2(5.15,7) v2(20.85,7) ; v2(23.1,7) v2(38.85,7)
N6649358: length 5.2
  TOP w0.2: J2.7 38.48,64.97 38.85,64.97 39.56,64.26 C5.1 39.56,62.51 39.61,62.46 R7.2
N6649402: length 4.1
  TOP w0.2: R1.2 R2.1 29.88,65.07 29.9,65.08 J2.1
N6649481: length 4.7
  TOP w0.2: R5.2 R6.1 36.46,64.45 J2.5
N6649490: length 4.4
  TOP w0.2: R3.2 R4.1 33.14,65.23 J2.3

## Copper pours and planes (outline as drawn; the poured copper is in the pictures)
GND on TOP, BOTTOM, INNER LAYER 2, INNER LAYER 3: 0.15,45.62 0.15,75.85 43.85,75.85 43.85,45.62 29.48,31.25 29.48,26.32 41.83,13.98 41.83,0.15 2.18,0.15 2.18,13.92 14.57,26.32 14.57,31.2
RF1 on TOP (solid shape): 42.63,52.88 41.31,52.88 40.87,53.2 40.87,53.31 41.31,53.62 42.63,53.62
RF2 on TOP (solid shape): 33.06,38.39 34,37.45 33.47,36.92 32.53,37.85 32.45,38.39 32.53,38.48
RF3 on TOP (solid shape): 11.56,38.39 11.47,37.86 10.53,36.92 10,37.45 10.94,38.39 11.47,38.47
RF4 on TOP (solid shape): 3.13,53.3 3.13,53.19 2.69,52.88 1.37,52.88 1.37,53.62 2.69,53.62
RFC on TOP (solid shape): 22.11,73.31 21.79,72.87 21.68,72.87 21.37,73.31 21.37,74.63 22.11,74.63
N6631865 on TOP (solid shape): 5.13,7.05 5.13,6.94 4.69,6.62 3.37,6.62 3.37,7.38 4.69,7.38
N6631865 on TOP (solid shape): 40.63,6.62 39.31,6.62 38.87,6.95 38.87,7.06 39.31,7.38 40.63,7.38

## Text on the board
BOTTOM: PRT-82544-01 | LAYER 4 (SECONDARY SIDE) | L4
Board Geometry/Soldermask Bottom: SOLDERMASK (SECONDARY SIDE) | SB
Ref Des/Silkscreen Bottom: SILKSCREEN (SECONDARY SIDE) | BS
Board Geometry/Soldermask Top: SOLDERMASK (PRIMARY SIDE) | TM
Ref Des/Silkscreen Top: SPxT 4mm x 4mm 24L QFN | BURIED RF TL | PRT-82544-01 | SILKSCREEN (PRIMARY SIDE) | TS
INNER LAYER 2: LAYER 2 (SIGNAL/GND) | L2
INNER LAYER 3: LAYER 3 (GROUND) | L3
DIMENSION: SOLDER PASTE (PRIMARY SIDE) | TP
BODY_CENTER: SOLDER PASTE (SECONDARY SIDE) | BP
FILM_TITLE_BLOCK: 10/19/22
User.7: 0.072136 [0.00284] | 0.4572 [0.018] | 1 oz. FINISHED | 0.032 | MEGTRON-6 | ISOLA 370HR | 0.8128 | [0.003]
User.10: 15D. MICROVIAS SHALL BE PLATED SHUT AND PLANNARIZED. VOIDS IN MICROVIAS SHALL BE LIMITED PER IPC-6012.
User.14: FIG | FINISHED SIZE | 0.127 | ALL UNITS ARE IN MILLIMETERS | TOLERANCE | +0.0/-0.0 | PLATED | QTY | 14 | TOTAL HOLES: | TOP to INNER LAYER 2
User.15: FIG | FINISHED SIZE | 0.2032 | 1.0 | 3.8 | ALL UNITS ARE IN MILLIMETERS | TOLERANCE | +0.0/-0.0 | +0.075/-0.075 | +0.05/-0.05 | PLATED | NON-PLATED | QTY | 1700 | 10 | 3 | 1713 | TOTAL HOLES: | TOP to BOTTOM
User.18: R2 | R1 | R4 | R3 | C7 | R6 | R5 | R7 | R8 | C4 | C5 | C3 | C1 | C2 | RF4 | RFCAL1 | TOP ASSEMBLY | RFC | U1 | RFCAL2 | RF1 | J1 | 2 | 1 | J2 | 8 | 7 | RF3 | RF2
